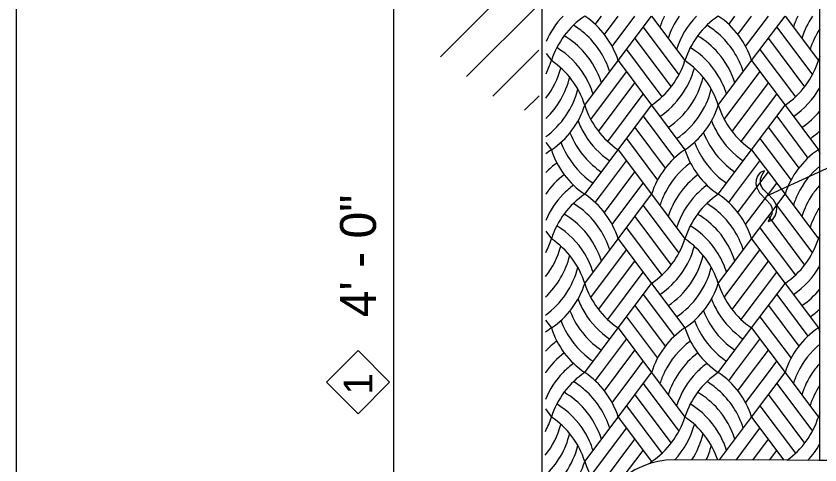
# Model space of a CAD drawing. Extents: x 99861 to 103151, y 100000 to 102076.
# Drawn here: x 99861 to 100218.6, y 101045 to 101244.5 of the extents above; entities that cross this region are included whole.
import ezdxf

# ---------------------------------------------------------------- set-up
doc = ezdxf.new("R2010")
doc.units = 0
for name, color, linetype in [('Level 1', 7, 'Continuous'), ('Level 10', 7, 'Continuous'), ('Level 15', 7, 'Continuous'), ('Level 2', 7, 'Continuous'), ('Level 20', 7, 'Continuous'), ('Level 6', 7, 'Continuous')]:
    doc.layers.add(name, color=color, linetype=linetype)

msp = doc.modelspace()

# ---------------------------------------------------------------- linework, layer by layer
at = {"layer": 'Level 1'}
for p, q in [((100153.9, 101047.21), (100153.89, 101047.21)), ((100203.89, 101047.09), (100153.9, 101047.21)), ((100203.9, 101047.09), (100203.89, 101047.09)), ((100218.17, 101047), (100203.9, 101047.09)), ((100312, 101046.45), (100218.25, 101047))]:
    msp.add_line(p, q, dxfattribs=at)
msp.add_lwpolyline([(99861, 100000), (103150, 100000), (103150, 102076), (99861, 102076)], close=True, dxfattribs=at)
msp.add_arc((100153.89, 101010.33), 36.88, 90, 180, dxfattribs=at)
at = {"layer": 'Level 10'}
for p, q in [((100049.86, 101226.36), (100093.48, 101269.99)), ((100061.45, 101217.59), (100093.54, 101249.68)), ((100073.12, 101208.9), (100093.61, 101229.38)), ((100073.12, 101208.9), (100093.61, 101229.38)), ((100087.24, 101202.65), (100093.67, 101209.08))]:
    msp.add_line(p, q, dxfattribs=at)
at = {"layer": 'Level 15'}
for p, q in [((100029.13, 100943.99), (100029.13, 101333.89)), ((100194.8, 101164.45), (100264.76, 101196.68))]:
    msp.add_line(p, q, dxfattribs=at)
at = {"layer": 'Level 2'}
for p, q in [((100095.13, 100943.99), (100095.13, 101334.14)), ((100218.59, 101047), (100218.59, 101309.27))]:
    msp.add_line(p, q, dxfattribs=at)
at = {"layer": 'Level 20'}
for p, q in [((100192.04, 101174.98), (100190.93, 101173.33)), ((100194.04, 101175.66), (100192.04, 101174.98)), ((100192.87, 101173.54), (100194.04, 101175.66)), ((100190.3, 101171.65), (100190.16, 101169.95)), ((100190.93, 101173.33), (100190.3, 101171.65)), ((100192.15, 101170.55), (100192.27, 101171.91)), ((100192.27, 101171.91), (100192.87, 101173.54)), ((100190.16, 101169.95), (100190.51, 101168.22)), ((100190.51, 101168.22), (100191.82, 101165.84)), ((100192.4, 101169.24), (100192.15, 101170.55)), ((100193.34, 101167.57), (100192.4, 101169.24)), ((100191.82, 101165.84), (100194.88, 101162.66)), ((100195.1, 101165.73), (100193.34, 101167.57)), ((100198, 101162.83), (100195.1, 101165.73)), ((100194.88, 101162.66), (100196.56, 101160.91)), ((100196.56, 101160.91), (100197.26, 101159.59)), ((100199.14, 101160.65), (100198, 101162.83)), ((100199.47, 101159.02), (100199.14, 101160.65)), ((100197.47, 101158.18), (100197.21, 101156.56)), ((100197.26, 101159.59), (100197.47, 101158.18)), ((100198.72, 101155.74), (100199.33, 101157.41)), ((100199.33, 101157.41), (100199.47, 101159.02)), ((100197.21, 101156.56), (100195.6, 101153.23)), ((100195.6, 101153.23), (100197.6, 101153.91)), ((100197.6, 101153.91), (100198.72, 101155.74))]:
    msp.add_line(p, q, dxfattribs=at)
msp.add_lwpolyline([(99999.09, 101081.76), (100013.13, 101095.8), (100027.18, 101081.76), (100013.13, 101067.72)], close=True, dxfattribs=at)
at = {"layer": 'Level 6'}
for p, q in [((100118.68, 101240.76), (100121.45, 101244.45)), ((100122.76, 101236.3), (100128.88, 101244.45)), ((100126.2, 101230.99), (100136.3, 101244.45)), ((100128.88, 101224.65), (100143.72, 101244.45)), ((100143.72, 101244.45), (100158.57, 101224.65)), ((100178.08, 101240.76), (100180.85, 101244.45)), ((100182.15, 101236.3), (100188.27, 101244.45)), ((100185.6, 101230.99), (100195.7, 101244.45)), ((100188.27, 101224.65), (100203.12, 101244.45)), ((100203.12, 101244.45), (100217.97, 101224.65)), ((100140.01, 101239.5), (100155.9, 101218.32)), ((100199.41, 101239.5), (100215.3, 101218.32)), ((100136.3, 101234.55), (100152.46, 101213.01)), ((100195.7, 101234.55), (100211.85, 101213.01)), ((100132.59, 101229.6), (100148.38, 101208.55)), ((100191.98, 101229.6), (100207.77, 101208.55)), ((100096.8, 101227.83), (100099.18, 101224.65)), ((100114.03, 101204.86), (100128.88, 101224.65)), ((100128.88, 101224.65), (100143.72, 101204.86)), ((100173.42, 101204.86), (100188.27, 101224.65)), ((100188.27, 101224.65), (100203.12, 101204.86)), ((100116.7, 101198.52), (100132.59, 101219.7)), ((100176.1, 101198.52), (100191.98, 101219.7)), ((100120.14, 101193.21), (100136.3, 101214.75)), ((100179.54, 101193.21), (100195.7, 101214.75)), ((100124.22, 101188.75), (100140.01, 101209.81)), ((100183.62, 101188.75), (100199.41, 101209.81)), ((100128.88, 101185.06), (100143.72, 101204.86)), ((100143.72, 101204.86), (100158.57, 101185.06)), ((100188.27, 101185.06), (100203.12, 101204.86)), ((100203.12, 101204.86), (100217.97, 101185.06)), ((100140.01, 101199.91), (100153.92, 101181.36)), ((100199.41, 101199.91), (100213.32, 101181.36)), ((100136.3, 101194.96), (100149.84, 101176.9)), ((100195.7, 101194.96), (100209.24, 101176.9)), ((100132.59, 101190.01), (100146.4, 101171.59)), ((100191.98, 101190.01), (100205.79, 101171.59)), ((100096.72, 101188.33), (100099.18, 101185.06)), ((100114.03, 101165.26), (100128.88, 101185.06)), ((100128.88, 101185.06), (100143.72, 101165.26)), ((100173.42, 101165.26), (100188.27, 101185.06)), ((100188.27, 101185.06), (100203.12, 101165.26)), ((100121.45, 101165.26), (100132.59, 101180.11)), ((100180.85, 101165.26), (100191.98, 101180.11)), ((100128.88, 101165.26), (100136.3, 101175.16)), ((100188.27, 101165.26), (100195.7, 101175.16)), ((100136.3, 101165.26), (100140.01, 101170.21)), ((100195.7, 101165.26), (100199.41, 101170.21)), ((100118.68, 101161.56), (100121.45, 101165.26)), ((100122.76, 101157.1), (100128.88, 101165.26)), ((100126.2, 101151.79), (100136.3, 101165.26)), ((100128.88, 101145.46), (100143.72, 101165.26)), ((100143.72, 101165.26), (100158.57, 101145.46)), ((100178.08, 101161.56), (100180.85, 101165.26)), ((100182.15, 101157.1), (100188.27, 101165.26)), ((100185.6, 101151.79), (100195.7, 101165.26)), ((100188.27, 101145.46), (100203.12, 101165.26)), ((100203.12, 101165.26), (100217.97, 101145.46)), ((100140.01, 101160.31), (100155.9, 101139.12)), ((100199.41, 101160.31), (100215.3, 101139.12)), ((100136.3, 101155.36), (100152.46, 101133.82)), ((100195.7, 101155.36), (100211.85, 101133.82)), ((100132.59, 101150.41), (100148.38, 101129.35)), ((100191.98, 101150.41), (100207.77, 101129.35)), ((100096.65, 101148.84), (100099.18, 101145.46)), ((100114.03, 101125.66), (100128.88, 101145.46)), ((100128.88, 101145.46), (100143.72, 101125.66)), ((100173.42, 101125.66), (100188.27, 101145.46)), ((100188.27, 101145.46), (100203.12, 101125.66)), ((100116.7, 101119.33), (100132.59, 101140.51)), ((100176.1, 101119.33), (100191.98, 101140.51)), ((100120.14, 101114.02), (100136.3, 101135.56)), ((100179.54, 101114.02), (100195.7, 101135.56)), ((100124.22, 101109.55), (100140.01, 101130.61)), ((100183.62, 101109.55), (100199.41, 101130.61)), ((100128.88, 101105.86), (100143.72, 101125.66)), ((100143.72, 101125.66), (100158.57, 101105.86)), ((100188.27, 101105.86), (100203.12, 101125.66)), ((100203.12, 101125.66), (100217.97, 101105.86)), ((100140.01, 101120.71), (100153.92, 101102.17)), ((100199.41, 101120.71), (100213.32, 101102.17)), ((100136.3, 101115.76), (100149.84, 101097.7)), ((100195.7, 101115.76), (100209.24, 101097.7)), ((100132.59, 101110.81), (100146.4, 101092.4)), ((100191.98, 101110.81), (100205.79, 101092.4)), ((100096.57, 101109.34), (100099.18, 101105.86)), ((100114.03, 101086.06), (100128.88, 101105.86)), ((100128.88, 101105.86), (100143.72, 101086.06)), ((100173.42, 101086.06), (100188.27, 101105.86)), ((100188.27, 101105.86), (100203.12, 101086.06)), ((100121.45, 101086.06), (100132.59, 101100.91)), ((100180.85, 101086.06), (100191.98, 101100.91)), ((100128.88, 101086.06), (100136.3, 101095.96)), ((100188.27, 101086.06), (100195.7, 101095.96)), ((100136.3, 101086.06), (100140.01, 101091.01)), ((100195.7, 101086.06), (100199.41, 101091.01)), ((100118.68, 101082.37), (100121.45, 101086.06)), ((100122.76, 101077.9), (100128.88, 101086.06)), ((100126.2, 101072.6), (100136.3, 101086.06)), ((100128.88, 101066.26), (100143.72, 101086.06)), ((100143.72, 101086.06), (100158.57, 101066.26)), ((100178.08, 101082.37), (100180.85, 101086.06)), ((100182.15, 101077.9), (100188.27, 101086.06)), ((100185.6, 101072.6), (100195.7, 101086.06)), ((100188.27, 101066.26), (100203.12, 101086.06)), ((100203.12, 101086.06), (100217.97, 101066.26)), ((100140.01, 101081.11), (100155.9, 101059.93)), ((100199.41, 101081.11), (100215.3, 101059.93)), ((100136.3, 101076.16), (100152.46, 101054.62)), ((100195.7, 101076.16), (100211.85, 101054.62)), ((100132.59, 101071.21), (100148.38, 101050.16)), ((100191.98, 101071.21), (100207.77, 101050.16)), ((100096.49, 101069.84), (100099.18, 101066.26)), ((100114.03, 101046.46), (100128.88, 101066.26)), ((100128.88, 101066.26), (100143.72, 101046.46)), ((100173.95, 101047.16), (100188.27, 101066.26)), ((100188.27, 101066.26), (100202.65, 101047.09)), ((100116.7, 101040.13), (100132.59, 101061.31)), ((100181.36, 101047.14), (100191.98, 101061.31)), ((100096.48, 101059.97), (100096.5, 101059.93)), ((100120.14, 101034.82), (100136.3, 101056.36)), ((100188.77, 101047.13), (100195.7, 101056.36)), ((100130.72, 101039.02), (100140.01, 101051.41)), ((100196.18, 101047.11), (100199.41, 101051.41)), ((100143.07, 101045.59), (100143.72, 101046.46)), ((100143.72, 101046.46), (100144.15, 101045.9))]:
    msp.add_line(p, q, dxfattribs=at)
for centre, start, end in [((100131.28, 101218.21), 135.7127, 156.5311), ((100134.99, 101213.27), 123.9036, 162.3566), ((100093.07, 101213.27), 17.6434, 56.0963), ((100183.25, 101228.11), 154.2265, 162.3566), ((100186.96, 101223.16), 145.491, 162.3566), ((100190.67, 101218.21), 135.7127, 162.3566), ((100194.38, 101213.27), 123.9036, 162.3566), ((100152.46, 101213.27), 17.6434, 56.0963), ((100242.64, 101228.11), 154.2265, 162.3566), ((100246.35, 101223.16), 145.491, 162.3566), ((100089.35, 101208.32), 48.9597, 58.5465), ((100148.75, 101208.32), 48.9597, 58.5465), ((100085.64, 101203.37), 40.9413, 59.3021), ((100089.35, 101208.32), 17.6434, 48.9597), ((100145.04, 101203.37), 40.9413, 59.3021), ((100148.75, 101208.32), 17.6434, 48.9597), ((100250.07, 101218.21), 146.8962, 162.3566), ((100081.93, 101198.42), 31.3316, 58.4874), ((100141.33, 101198.42), 31.3316, 58.4874), ((100085.64, 101203.37), 17.6434, 40.9414), ((100145.04, 101203.37), 17.6434, 40.9414), ((100253.78, 101213.27), 159.4675, 162.3566), ((100067.08, 101231.09), 322.1654, 345.0113), ((100063.37, 101236.04), 332.7636, 342.3566), ((100078.22, 101193.47), 17.6434, 56.0964), ((100122.76, 101236.04), 303.9036, 342.3566), ((100126.48, 101231.09), 303.9036, 345.0113), ((100137.61, 101193.47), 17.6434, 56.0964), ((100182.16, 101236.04), 303.9036, 342.3566), ((100197.01, 101193.47), 54.9504, 56.0964), ((100081.93, 101198.42), 17.6434, 31.3317), ((100141.32, 101198.42), 17.6434, 31.3317), ((100070.79, 101226.14), 313.6722, 346.3199), ((100130.19, 101226.14), 303.9036, 346.3199), ((100074.5, 101221.19), 306.2515, 345.7713), ((100133.9, 101221.19), 303.9036, 345.7713), ((100185.87, 101231.09), 303.9036, 330.5353), ((100078.22, 101216.24), 303.9036, 342.3566), ((100149.84, 101216.24), 197.6435, 236.0964), ((100137.61, 101216.24), 303.9036, 342.3566), ((100209.23, 101216.24), 197.6435, 236.0964), ((100189.58, 101226.14), 303.9036, 320.5219), ((100146.12, 101211.3), 200.8778, 211.332), ((100205.52, 101211.3), 200.8778, 211.332), ((100193.3, 101221.19), 303.9036, 312.305), ((100142.41, 101206.35), 201.4344, 220.9416), ((100146.12, 101211.3), 211.3319, 236.0964), ((100201.81, 101206.35), 201.4344, 220.9416), ((100205.52, 101211.3), 211.3319, 236.0964), ((100138.7, 101201.4), 200.2432, 228.9599), ((100198.1, 101201.4), 200.2432, 228.9599), ((100120.14, 101153.87), 123.9036, 128.5681), ((100134.99, 101196.45), 197.6434, 236.0964), ((100179.53, 101153.87), 123.9036, 162.3566), ((100194.38, 101196.45), 197.6434, 236.0964), ((100238.93, 101153.87), 123.9036, 162.3566), ((100197.01, 101216.24), 303.9036, 305.0496), ((100253.78, 101196.45), 197.6434, 200.5325), ((100123.85, 101148.92), 126.3063, 136.2746), ((100142.41, 101206.35), 220.9415, 236.0964), ((100183.25, 101148.92), 126.3063, 154.2266), ((100201.81, 101206.35), 220.9415, 236.0964), ((100242.64, 101148.92), 129.7993, 154.2266), ((100127.56, 101143.97), 127.1006, 145.2791), ((100138.7, 101201.4), 228.9599, 236.0964), ((100186.96, 101143.97), 127.1006, 145.4911), ((100198.09, 101201.4), 228.9599, 236.0964), ((100131.28, 101139.02), 126.331, 135.7128), ((100190.67, 101139.02), 126.331, 135.7128), ((100246.35, 101143.97), 137.637, 145.4911), ((100131.28, 101139.02), 135.7127, 157.1205), ((100134.99, 101134.07), 123.9036, 162.3566), ((100093.07, 101134.07), 17.6434, 56.0963), ((100183.25, 101148.92), 154.2265, 162.3566), ((100186.96, 101143.97), 145.491, 162.3566), ((100190.67, 101139.02), 135.7127, 162.3566), ((100194.38, 101134.07), 123.9036, 162.3566), ((100152.46, 101134.07), 17.6434, 56.0963), ((100242.64, 101148.92), 154.2265, 162.3566), ((100246.35, 101143.97), 145.491, 162.3566), ((100089.35, 101129.12), 48.9597, 58.5465), ((100148.75, 101129.12), 48.9597, 58.5465), ((100089.35, 101129.12), 17.6434, 48.9597), ((100148.75, 101129.12), 17.6434, 48.9597), ((100250.07, 101139.02), 146.8962, 162.3566), ((100085.64, 101124.17), 40.9413, 59.3021), ((100145.04, 101124.17), 40.9413, 59.3021), ((100081.93, 101119.22), 31.3316, 58.4874), ((100141.33, 101119.22), 31.3316, 58.4874), ((100085.64, 101124.17), 17.6434, 40.9414), ((100145.04, 101124.17), 17.6434, 40.9414), ((100253.78, 101134.07), 159.4675, 162.3566), ((100063.37, 101156.85), 332.2615, 342.3566), ((100078.22, 101114.27), 17.6434, 56.0964), ((100122.76, 101156.85), 303.9036, 342.3566), ((100137.61, 101114.27), 17.6434, 56.0964), ((100182.16, 101156.85), 303.9036, 342.3566), ((100197.01, 101114.27), 54.9504, 56.0964), ((100067.08, 101151.9), 321.7897, 345.0113), ((100126.48, 101151.9), 303.9036, 345.0113), ((100070.79, 101146.95), 313.3533, 346.3199), ((100081.93, 101119.22), 17.6434, 31.3317), ((100130.19, 101146.95), 303.9036, 346.3199), ((100141.32, 101119.22), 17.6434, 31.3317), ((100074.5, 101142), 305.9653, 345.7713), ((100133.9, 101142), 303.9036, 345.7713), ((100185.87, 101151.9), 303.9036, 330.5353), ((100078.22, 101137.05), 303.9036, 342.3566), ((100149.84, 101137.05), 197.6435, 236.0964), ((100137.61, 101137.05), 303.9036, 342.3566), ((100209.23, 101137.05), 197.6435, 236.0964), ((100189.58, 101146.95), 303.9036, 320.5219), ((100146.12, 101132.1), 200.8778, 211.332), ((100205.52, 101132.1), 200.8778, 211.332), ((100193.3, 101142), 303.9036, 312.305), ((100142.41, 101127.15), 201.4344, 220.9416), ((100146.12, 101132.1), 211.3319, 236.0964), ((100201.81, 101127.15), 201.4344, 220.9416), ((100205.52, 101132.1), 211.3319, 236.0964), ((100138.7, 101122.2), 200.2432, 228.9599), ((100198.1, 101122.2), 200.2432, 228.9599), ((100120.14, 101074.67), 123.9036, 128.8645), ((100134.99, 101117.25), 197.6434, 236.0964), ((100179.53, 101074.67), 123.9036, 162.3566), ((100194.38, 101117.25), 197.6434, 236.0964), ((100238.93, 101074.67), 123.9036, 162.3566), ((100197.01, 101137.05), 303.9036, 305.0496), ((100253.78, 101117.25), 197.6434, 200.5325), ((100123.85, 101069.72), 126.3063, 136.6103), ((100142.41, 101127.15), 220.9415, 236.0964), ((100183.25, 101069.72), 126.3063, 154.2266), ((100201.81, 101127.15), 220.9415, 236.0964), ((100242.64, 101069.72), 129.7993, 154.2266), ((100127.56, 101064.77), 127.1006, 145.4911), ((100138.7, 101122.2), 228.9599, 236.0964), ((100186.96, 101064.77), 127.1006, 145.4911), ((100198.09, 101122.2), 228.9599, 236.0964), ((100131.28, 101059.82), 126.331, 135.7128), ((100190.67, 101059.82), 126.331, 135.7128), ((100246.35, 101064.77), 137.637, 145.4911), ((100131.28, 101059.82), 135.7127, 157.7246), ((100127.56, 101064.77), 145.491, 145.6877), ((100134.99, 101054.87), 123.9036, 162.3566), ((100093.07, 101054.87), 17.6434, 56.0963), ((100183.25, 101069.72), 154.2265, 162.3566), ((100186.96, 101064.77), 145.491, 162.3566), ((100190.67, 101059.82), 135.7127, 162.3566), ((100194.38, 101054.87), 123.9036, 162.3566), ((100152.46, 101054.87), 17.6434, 56.0963), ((100242.64, 101069.72), 154.2265, 162.3566), ((100246.35, 101064.77), 145.491, 162.3566), ((100089.35, 101049.92), 48.9597, 58.5465), ((100148.75, 101049.92), 48.9597, 58.5465), ((100089.35, 101049.92), 17.6434, 48.9597), ((100148.75, 101049.92), 17.6434, 48.9597), ((100250.07, 101059.82), 146.8962, 162.3566), ((100085.64, 101044.97), 40.9413, 59.3021), ((100145.04, 101044.97), 40.9413, 59.3021), ((100081.93, 101040.02), 31.3316, 58.4874), ((100141.33, 101040.02), 31.3316, 58.4874), ((100085.64, 101044.97), 17.6434, 40.9414), ((100145.04, 101044.97), 17.6434, 40.9414), ((100253.78, 101054.87), 159.4675, 162.3566), ((100063.37, 101077.65), 331.7677, 342.3566), ((100078.22, 101035.07), 17.6434, 56.0964), ((100122.76, 101077.65), 303.9036, 342.3566), ((100137.61, 101035.07), 18.7682, 56.0964), ((100182.16, 101077.65), 305.5748, 342.3566), ((100197.01, 101035.07), 54.9504, 56.0964), ((100067.08, 101072.7), 321.4171, 345.0113), ((100126.48, 101072.7), 317.2845, 345.0113), ((100070.79, 101067.75), 313.036, 346.3199), ((100081.93, 101040.02), 17.6434, 31.3317), ((100130.19, 101067.75), 326.8296, 346.3199), ((100141.32, 101040.02), 17.6434, 31.3317), ((100074.5, 101062.8), 305.6801, 345.7713), ((100133.9, 101062.8), 335.4284, 345.7713), ((100185.87, 101072.7), 316.9135, 330.5353), ((100078.22, 101057.85), 303.9036, 342.3566), ((100149.84, 101057.85), 197.6435, 225.3531)]:
    msp.add_arc(centre, 37.58, start, end, dxfattribs=at)

# ---------------------------------------------------------------- texts
at = {"layer": 'Level 20'}
for s, height, p in [('4\' - 0"', 16, (100021.13, 101110.6)), ('1', 12.8, (100019.53, 101076.26))]:
    msp.add_text(s, height=height, rotation=90, dxfattribs=at).set_placement(p)

doc.saveas('drawing.dxf')
